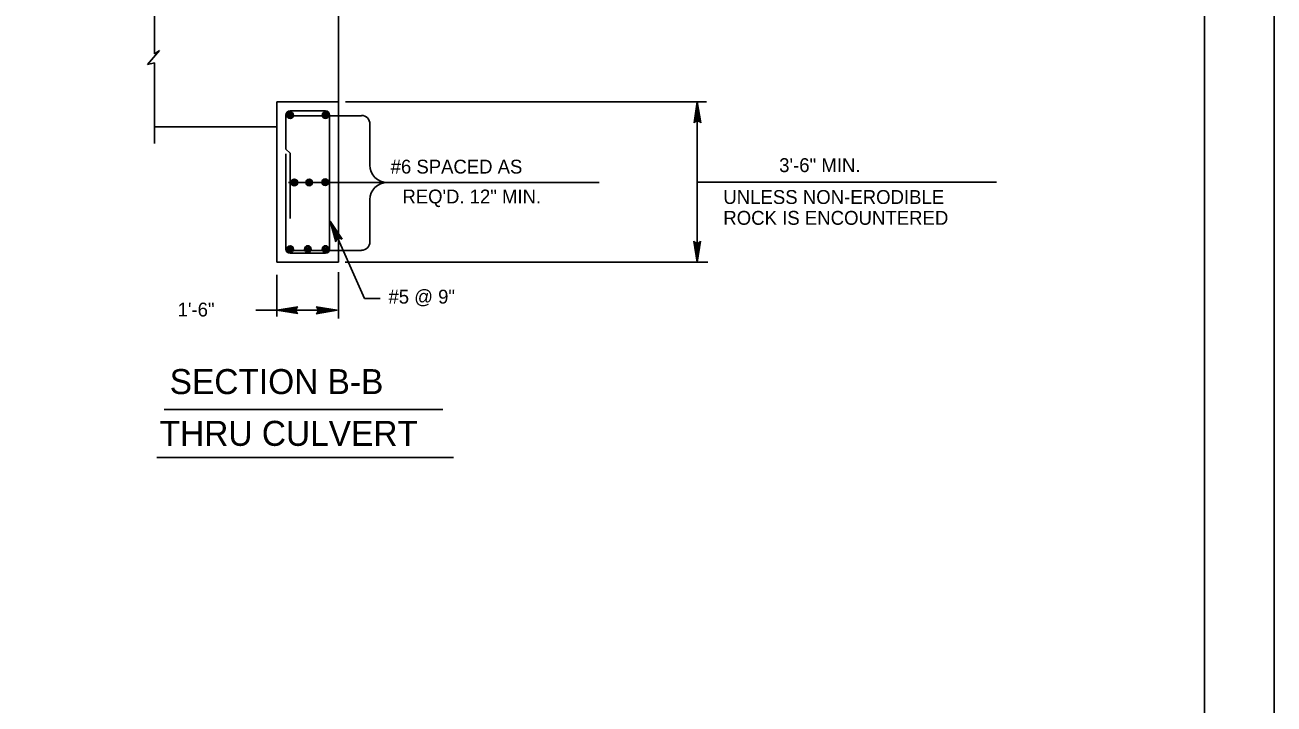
# Model space of a CAD drawing. Extents: x 639011 to 639866, y 298840 to 300028.
# Drawn here: x 639582.6 to 639852.3, y 299133.1 to 299279.7 of the extents above; entities that cross this region are included whole.
import ezdxf

# ---------------------------------------------------------------- set-up
doc = ezdxf.new("R2010")
doc.units = 0
doc.layers.add('2', color=7, linetype='Continuous')
doc.layers.add('PLT-BNDY', color=7, linetype='Continuous')

msp = doc.modelspace()

# ---------------------------------------------------------------- linework, layer by layer
at = {"layer": '2'}
for p, q in [((639837.26, 299418.83), (639837.26, 298854.83)), ((639650.28, 299357.31), (639650.28, 299228.46)), ((639610.53, 299297.46), (639610.53, 299273.46)), ((639611.58, 299274.21), (639609.03, 299271.21)), ((639610.53, 299273.46), (639611.58, 299274.21)), ((639609.03, 299271.21), (639610.53, 299271.51)), ((639610.53, 299271.51), (639610.53, 299254.11)), ((639636.93, 299263.11), (639636.93, 299228.46)), ((639636.93, 299263.11), (639650.28, 299263.11)), ((639651.78, 299263.11), (639729.68, 299263.11)), ((639727.02, 299258.55), (639727.73, 299263.11)), ((639727.73, 299263.11), (639727.21, 299258.78)), ((639727.53, 299258.94), (639727.73, 299263.11)), ((639727.73, 299263.11), (639727.73, 299228.46)), ((639727.73, 299263.11), (639727.96, 299258.94)), ((639728.28, 299258.79), (639727.73, 299263.11)), ((639727.73, 299263.11), (639728.49, 299258.55)), ((639727.73, 299263.11), (639727.74, 299258.94)), ((639638.88, 299260.26), (639638.88, 299252.91)), ((639639.78, 299261.16), (639647.43, 299261.16)), ((639639.78, 299260.11), (639655.23, 299260.11)), ((639648.33, 299260.26), (639648.33, 299231.31)), ((639636.93, 299257.71), (639610.53, 299257.71)), ((639637.08, 299257.71), (639637.05, 299257.71)), ((639657.03, 299258.31), (639657.03, 299249.46)), ((639727.21, 299258.78), (639727.02, 299258.55)), ((639727.21, 299258.78), (639727.53, 299258.94)), ((639727.53, 299258.94), (639727.96, 299258.94)), ((639727.96, 299258.94), (639728.28, 299258.79)), ((639728.49, 299258.55), (639728.28, 299258.79)), ((639639.78, 299252.01), (639638.88, 299252.91)), ((639638.88, 299251.86), (639638.88, 299231.31)), ((639639.78, 299252.01), (639639.78, 299237.91)), ((639639.48, 299245.71), (639660.52, 299245.71)), ((639660.78, 299245.71), (639674.13, 299245.71)), ((639660.78, 299245.71), (639706.5, 299245.71)), ((639660.78, 299245.71), (639671.73, 299245.71)), ((639727.73, 299245.78), (639792.31, 299245.78)), ((639657.03, 299241.96), (639657.03, 299232.96)), ((639648.48, 299237.31), (639655.83, 299220.66)), ((639649.98, 299233.41), (639648.48, 299237.31)), ((639648.48, 299237.31), (639649.76, 299233.14)), ((639649.67, 299232.85), (639648.48, 299237.31)), ((639648.48, 299237.31), (639650.38, 299233.59)), ((639650.73, 299233.58), (639648.48, 299237.31)), ((639648.48, 299237.31), (639651.01, 299233.45)), ((639648.48, 299237.31), (639650.18, 299233.5)), ((639649.76, 299233.14), (639649.67, 299232.85)), ((639649.76, 299233.14), (639649.98, 299233.41)), ((639649.98, 299233.41), (639650.38, 299233.59)), ((639650.38, 299233.59), (639650.73, 299233.58)), ((639651.01, 299233.45), (639650.73, 299233.58)), ((639727.73, 299228.46), (639726.97, 299233.01)), ((639726.97, 299233.01), (639727.18, 299232.78)), ((639728.43, 299233.02), (639727.73, 299228.46)), ((639728.24, 299232.79), (639728.43, 299233.02)), ((639639.78, 299231.01), (639655.23, 299231.01)), ((639639.78, 299230.41), (639647.43, 299230.41)), ((639727.49, 299232.62), (639727.18, 299232.78)), ((639727.18, 299232.78), (639727.73, 299228.46)), ((639727.93, 299232.63), (639727.49, 299232.62)), ((639727.73, 299228.46), (639727.49, 299232.62)), ((639727.73, 299228.46), (639727.71, 299232.62)), ((639727.73, 299228.46), (639728.24, 299232.79)), ((639727.93, 299232.63), (639727.73, 299228.46)), ((639728.24, 299232.79), (639727.93, 299232.63)), ((639636.93, 299228.46), (639650.28, 299228.46)), ((639651.68, 299228.46), (639729.98, 299228.46)), ((639636.93, 299225.76), (639636.93, 299216.76)), ((639650.28, 299226.36), (639650.28, 299216.31)), ((639655.83, 299220.66), (639659.28, 299220.66)), ((639632.43, 299218.11), (639636.93, 299218.11)), ((639636.93, 299218.11), (639641.48, 299218.87)), ((639641.25, 299218.66), (639636.93, 299218.11)), ((639636.93, 299218.11), (639641.09, 299218.34)), ((639636.93, 299218.11), (639641.1, 299218.13)), ((639636.93, 299218.11), (639649.98, 299218.11)), ((639641.1, 299217.91), (639636.93, 299218.11)), ((639636.93, 299218.11), (639641.26, 299217.59)), ((639641.49, 299217.4), (639636.93, 299218.11)), ((639641.09, 299218.34), (639641.25, 299218.66)), ((639641.1, 299217.91), (639641.09, 299218.34)), ((639641.26, 299217.59), (639641.1, 299217.91)), ((639641.48, 299218.87), (639641.25, 299218.66)), ((639641.26, 299217.59), (639641.49, 299217.4)), ((639645.65, 299218.62), (639645.42, 299218.82)), ((639645.42, 299218.82), (639649.98, 299218.11)), ((639649.98, 299218.11), (639645.43, 299217.35)), ((639645.43, 299217.35), (639645.66, 299217.56)), ((639645.65, 299218.62), (639645.81, 299218.31)), ((639649.98, 299218.11), (639645.65, 299218.62)), ((639645.66, 299217.56), (639649.98, 299218.11)), ((639645.81, 299217.87), (639645.66, 299217.56)), ((639645.81, 299218.31), (639649.98, 299218.11)), ((639645.81, 299218.31), (639645.81, 299217.87)), ((639649.98, 299218.11), (639645.81, 299217.87)), ((639649.98, 299218.11), (639645.81, 299218.09)), ((639612.64, 299196.71), (639672.77, 299196.71)), ((639611.03, 299186.28), (639675.08, 299186.28))]:
    msp.add_line(p, q, dxfattribs=at)
for centre, radius in [((639639.83, 299260.21), 0.715), ((639639.83, 299260.21), 0.511), ((639639.83, 299260.21), 0.279), ((639639.83, 299260.21), 0.141), ((639639.83, 299260.21), 0.0604), ((639647.44, 299260.26), 0.715), ((639647.44, 299260.26), 0.511), ((639647.44, 299260.26), 0.279), ((639647.44, 299260.26), 0.141), ((639647.44, 299260.26), 0.0604), ((639647.37, 299245.76), 0.715), ((639640.71, 299245.7), 0.715), ((639640.71, 299245.7), 0.511), ((639640.71, 299245.7), 0.279), ((639640.71, 299245.7), 0.141), ((639640.71, 299245.7), 0.0604), ((639643.92, 299245.7), 0.715), ((639643.92, 299245.7), 0.511), ((639643.92, 299245.7), 0.279), ((639643.92, 299245.7), 0.141), ((639643.92, 299245.7), 0.0604), ((639647.37, 299245.76), 0.511), ((639647.37, 299245.76), 0.279), ((639647.37, 299245.76), 0.141), ((639647.37, 299245.76), 0.0604), ((639639.83, 299231.31), 0.715), ((639639.83, 299231.31), 0.511), ((639639.83, 299231.31), 0.279), ((639639.83, 299231.31), 0.141), ((639639.83, 299231.31), 0.0604), ((639643.62, 299231.33), 0.715), ((639643.62, 299231.33), 0.511), ((639643.62, 299231.33), 0.279), ((639643.62, 299231.33), 0.141), ((639643.62, 299231.33), 0.0604), ((639647.44, 299231.33), 0.715), ((639647.44, 299231.33), 0.511), ((639647.44, 299231.33), 0.279), ((639647.44, 299231.33), 0.141), ((639647.44, 299231.33), 0.0604)]:
    msp.add_circle(centre, radius, dxfattribs=at)
for centre, radius, start, end in [((639639.78, 299260.26), 0.9, 90, 180), ((639647.43, 299260.26), 0.9, 0, 90), ((639655.18, 299258.31), 1.86, 0, 90), ((639660.75, 299249.43), 3.71, 180, 270), ((639660.75, 299242), 3.71, 90, 180), ((639639.78, 299231.31), 0.9, 180, 270), ((639647.43, 299231.31), 0.9, 270, 0), ((639655.18, 299232.91), 1.86, 270, 0)]:
    msp.add_arc(centre, radius, start, end, dxfattribs=at)
at = {"layer": 'PLT-BNDY'}
msp.add_lwpolyline([(639011.26, 299433.83), (639852.26, 299433.83), (639852.26, 298839.83), (639011.26, 298839.83)], close=True, dxfattribs=at)

# ---------------------------------------------------------------- texts
at = {"layer": '2'}
for s, height, p in [('#6 SPACED AS', 2.988, (639661.52, 299247.63)), ('3\'-6" MIN.', 3, (639745.4, 299247.94)), ('REQ\'D. 12" MIN.', 2.988, (639664.05, 299241.18)), ('UNLESS NON-ERODIBLE', 3, (639733.34, 299241.06)), ('ROCK IS ENCOUNTERED', 3, (639733.34, 299236.56)), ('#5 @ 9"', 2.988, (639661.04, 299219.55)), ('1\'-6"', 2.988, (639615.52, 299216.76)), ('SECTION B-B', 5.4, (639613.8, 299200.01)), ('THRU CULVERT', 5.4, (639611.63, 299188.83))]:
    msp.add_text(s, height=height, dxfattribs=at).set_placement(p)

doc.saveas('drawing.dxf')
